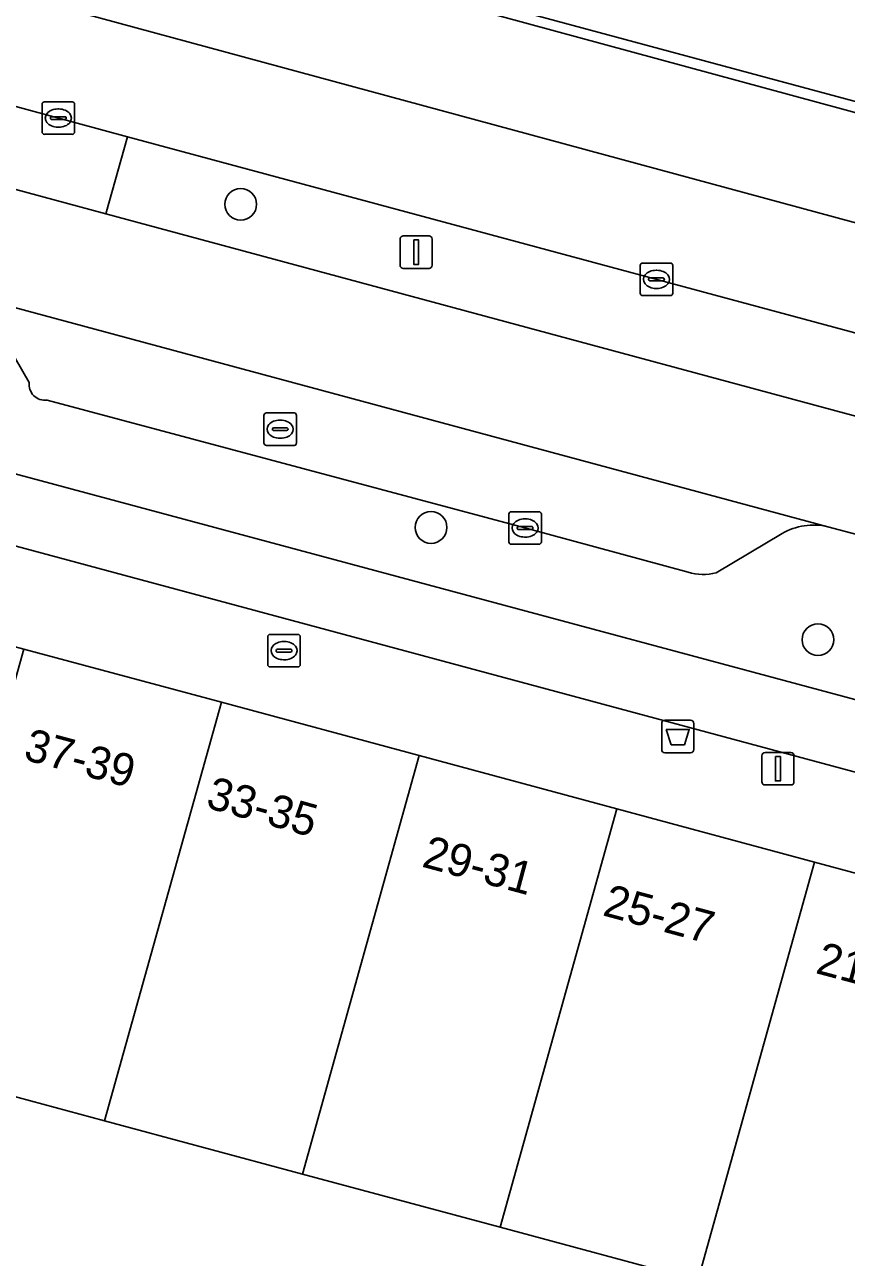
# Model space of a CAD drawing. Extents: x 160675 to 161153, y 383241 to 383714.
# Drawn here: x 160794.67 to 160819.96, y 383564.02 to 383601.94 of the extents above; entities that cross this region are included whole.
import ezdxf

# ---------------------------------------------------------------- set-up
doc = ezdxf.new("R2010")
doc.units = 0
for name, color, linetype in [('IMGEO_Afvalbak', 7, 'Continuous'), ('IMGEO_Berm_groen', 7, 'Continuous'), ('IMGEO_Berm_open', 7, 'Continuous'), ('IMGEO_Boom', 7, 'Continuous'), ('IMGEO_Brandkraan', 7, 'Continuous'), ('IMGEO_Erf', 7, 'Continuous'), ('IMGEO_Fietspad_gesloten', 7, 'Continuous'), ('IMGEO_Kolk', 7, 'Continuous'), ('IMGEO_Lichtmast', 7, 'Continuous'), ('IMGEO_OVBaan_gesloten', 7, 'Continuous'), ('IMGEO_Pand', 7, 'Continuous'), ('IMGEO_Pand_nummerreeks', 7, 'Continuous'), ('IMGEO_Parkeervlak_open', 7, 'Continuous'), ('IMGEO_Rijbaan_lokaal_gesloten', 7, 'Continuous'), ('IMGEO_Rioolput', 7, 'Continuous'), ('IMGEO_Voetpad_open', 7, 'Continuous')]:
    doc.layers.add(name, color=color, linetype=linetype)

msp = doc.modelspace()

# ---------------------------------------------------------------- linework, layer by layer
at = {"layer": 'IMGEO_Afvalbak'}
for p, q in [((160814.275, 383579.646), (160814.275, 383580.446)), ((160814.275, 383580.446), (160814.275, 383579.646)), ((160814.375, 383580.546), (160815.165, 383580.546)), ((160815.165, 383580.546), (160814.375, 383580.546)), ((160815.265, 383580.446), (160815.265, 383579.646)), ((160815.265, 383579.646), (160815.265, 383580.446)), ((160815.165, 383579.546), (160814.375, 383579.546)), ((160814.375, 383579.546), (160815.165, 383579.546))]:
    msp.add_line(p, q, dxfattribs=at)
msp.add_lwpolyline([(160814.418, 383580.26), (160815.122, 383580.26), (160814.973, 383579.79), (160814.567, 383579.79), (160814.418, 383580.26)], dxfattribs=at)
for centre, start, end in [((160814.375, 383580.446), 90, 180), ((160814.375, 383580.446), 90, 180), ((160815.165, 383580.446), 0, 90), ((160815.165, 383580.446), 360, 90), ((160814.375, 383579.646), 180, 270), ((160814.375, 383579.646), 180, 270), ((160815.165, 383579.646), 270, 0), ((160815.165, 383579.646), 270, 0)]:
    msp.add_arc(centre, 0.1, start, end, dxfattribs=at)
at = {"layer": 'IMGEO_Berm_groen'}
msp.add_lwpolyline([(160870.684, 383578.867), (160797.835, 383598.49), (160797.171, 383596.125), (160869.874, 383576.512), (160913.282, 383564.496)], dxfattribs=at)
at = {"layer": 'IMGEO_Berm_open'}
for points in [[(160771.691, 383612.444), (160783.094, 383609.33), (160861.613, 383588.006), (160861.742, 383588.359), (160845.226, 383592.848), (160809.68, 383602.419), (160784.127, 383609.308)], [(160753.356, 383599.164), (160754.374, 383598.874), (160872.54, 383567.128), (160873.601, 383566.834), (160874.194, 383569.11), (160871.092, 383569.968), (160860.355, 383572.895)], [(160794.817, 383590.934), (160793.746, 383592.772)], [(160815.088, 383585.095), (160810.069, 383586.459), (160795.367, 383590.393)], [(160826.28, 383584.667), (160819.386, 383586.497)], [(160817.978, 383586.286), (160815.949, 383585.082)]]:
    msp.add_lwpolyline(points, dxfattribs=at)
for centre, radius, start, end in [((160795.295, 383590.87), 0.482, 172.3842, 278.5611), ((160818.946, 383584.63), 1.918, 76.7407, 120.3049), ((160815.542, 383586.616), 1.587, 253.3984, 284.8716)]:
    msp.add_arc(centre, radius, start, end, dxfattribs=at)
at = {"layer": 'IMGEO_Boom'}
for centre in [(160801.324, 383596.414), (160807.18, 383586.475), (160819.082, 383583.023)]:
    msp.add_circle(centre, 0.489, dxfattribs=at)
at = {"layer": 'IMGEO_Brandkraan'}
for p, q in [((160802.155, 383582.259), (160802.155, 383583.111)), ((160802.23, 383583.185), (160803.082, 383583.185)), ((160802.643, 383582.965), (160802.668, 383582.965)), ((160803.156, 383583.111), (160803.156, 383582.259)), ((160802.414, 383582.679), (160802.414, 383582.691)), ((160802.852, 383582.642), (160802.454, 383582.642)), ((160802.457, 383582.728), (160802.855, 383582.728)), ((160802.898, 383582.691), (160802.898, 383582.679)), ((160803.082, 383582.185), (160802.23, 383582.185)), ((160802.666, 383582.405), (160802.641, 383582.405))]:
    msp.add_line(p, q, dxfattribs=at)
for points in [[(160802.155, 383582.259), (160802.155, 383583.111)], [(160802.23, 383583.185), (160803.082, 383583.185)], [(160803.156, 383583.111), (160803.156, 383582.259)], [(160803.082, 383582.185), (160802.23, 383582.185)]]:
    msp.add_lwpolyline(points, dxfattribs=at)
for centre, radius, start, end in [((160802.232, 383583.109), 0.0765, 91.552, 178.448), ((160802.232, 383583.109), 0.0765, 91.552, 178.448), ((160803.08, 383583.109), 0.0765, 1.552, 88.448), ((160803.08, 383583.109), 0.0765, 1.552, 88.448), ((160802.454, 383582.688), 0.0403, 85.8775, 175.7526), ((160802.451, 383582.678), 0.0366, 178.938, 274.7102), ((160802.855, 383582.685), 0.043, 264.8664, 352.4533), ((160802.859, 383582.69), 0.0386, 1.7309, 96.639), ((160802.232, 383582.261), 0.0765, 181.552, 268.448), ((160802.232, 383582.261), 0.0765, 181.552, 268.448), ((160803.08, 383582.261), 0.0765, 271.552, 358.448), ((160803.08, 383582.261), 0.0765, 271.552, 358.448)]:
    msp.add_arc(centre, radius, start, end, dxfattribs=at)
for centre, major_axis, ratio, start_param, end_param in [((160802.642, 383582.685), (-0.387, 0.002), 0.722429, 4.712389, 7.853982), ((160802.667, 383582.685), (-0.39, 0.002), 0.717154, 1.570796, 4.712389)]:
    msp.add_ellipse(centre, major_axis=major_axis, ratio=ratio, start_param=start_param, end_param=end_param, dxfattribs=at)
at = {"layer": 'IMGEO_Erf'}
msp.add_lwpolyline([(160815.386, 383563.308), (160809.303, 383564.947), (160803.219, 383566.585), (160797.136, 383568.224), (160791.052, 383569.862), (160784.969, 383571.501), (160778.885, 383573.14), (160772.802, 383574.778), (160766.719, 383576.417)], dxfattribs=at)
at = {"layer": 'IMGEO_Fietspad_gesloten'}
for points in [[(160741.54, 383600.127), (160851.652, 383570.489), (160869.912, 383565.633), (160904.417, 383556.04)], [(160904.814, 383558.169), (160877.012, 383565.887), (160875.567, 383566.288), (160873.601, 383566.834), (160872.54, 383567.128), (160754.374, 383598.874)]]:
    msp.add_lwpolyline(points, dxfattribs=at)
at = {"layer": 'IMGEO_Kolk'}
for p, q in [((160795.211, 383598.641), (160795.211, 383599.493)), ((160795.286, 383599.567), (160796.138, 383599.567)), ((160795.699, 383599.347), (160795.724, 383599.347)), ((160796.212, 383599.493), (160796.212, 383598.641)), ((160795.47, 383599.061), (160795.47, 383599.073)), ((160795.908, 383599.024), (160795.51, 383599.024)), ((160795.513, 383599.11), (160795.911, 383599.11)), ((160795.954, 383599.073), (160795.954, 383599.061)), ((160796.138, 383598.567), (160795.286, 383598.567)), ((160795.722, 383598.787), (160795.697, 383598.787)), ((160813.614, 383593.679), (160813.614, 383594.531)), ((160813.689, 383594.605), (160814.541, 383594.605)), ((160814.102, 383594.385), (160814.127, 383594.385)), ((160814.615, 383594.531), (160814.615, 383593.679)), ((160813.873, 383594.099), (160813.873, 383594.111)), ((160814.311, 383594.062), (160813.913, 383594.062)), ((160813.916, 383594.148), (160814.314, 383594.148)), ((160814.357, 383594.111), (160814.357, 383594.099)), ((160814.541, 383593.605), (160813.689, 383593.605)), ((160814.125, 383593.825), (160814.1, 383593.825)), ((160809.572, 383586.032), (160809.572, 383586.884)), ((160809.647, 383586.958), (160810.499, 383586.958)), ((160810.06, 383586.738), (160810.085, 383586.738)), ((160810.573, 383586.884), (160810.573, 383586.032)), ((160809.831, 383586.452), (160809.831, 383586.464)), ((160810.269, 383586.415), (160809.871, 383586.415)), ((160809.874, 383586.501), (160810.272, 383586.501)), ((160810.315, 383586.464), (160810.315, 383586.452)), ((160810.499, 383585.958), (160809.647, 383585.958)), ((160810.083, 383586.178), (160810.058, 383586.178))]:
    msp.add_line(p, q, dxfattribs=at)
for points in [[(160795.211, 383598.641), (160795.211, 383599.493)], [(160795.286, 383599.567), (160796.138, 383599.567)], [(160796.212, 383599.493), (160796.212, 383598.641)], [(160796.138, 383598.567), (160795.286, 383598.567)], [(160813.614, 383593.679), (160813.614, 383594.531)], [(160813.689, 383594.605), (160814.541, 383594.605)], [(160814.615, 383594.531), (160814.615, 383593.679)], [(160814.541, 383593.605), (160813.689, 383593.605)], [(160809.572, 383586.032), (160809.572, 383586.884)], [(160809.647, 383586.958), (160810.499, 383586.958)], [(160810.573, 383586.884), (160810.573, 383586.032)], [(160810.499, 383585.958), (160809.647, 383585.958)]]:
    msp.add_lwpolyline(points, dxfattribs=at)
for centre, radius, start, end in [((160795.288, 383599.491), 0.0765, 91.552, 178.448), ((160795.288, 383599.491), 0.0765, 91.552, 178.448), ((160796.136, 383599.491), 0.0765, 1.552, 88.448), ((160796.136, 383599.491), 0.0765, 1.552, 88.448), ((160795.51, 383599.07), 0.0403, 85.8775, 175.7526), ((160795.507, 383599.06), 0.0366, 178.938, 274.7102), ((160795.911, 383599.067), 0.043, 264.8664, 352.4533), ((160795.915, 383599.072), 0.0386, 1.7309, 96.639), ((160795.288, 383598.643), 0.0765, 181.552, 268.448), ((160795.288, 383598.643), 0.0765, 181.552, 268.448), ((160796.136, 383598.643), 0.0765, 271.552, 358.448), ((160796.136, 383598.643), 0.0765, 271.552, 358.448), ((160813.691, 383594.529), 0.0765, 91.552, 178.448), ((160813.691, 383594.529), 0.0765, 91.552, 178.448), ((160814.539, 383594.529), 0.0765, 1.552, 88.448), ((160814.539, 383594.529), 0.0765, 1.552, 88.448), ((160813.913, 383594.108), 0.0403, 85.8775, 175.7526), ((160813.91, 383594.098), 0.0366, 178.938, 274.7102), ((160814.314, 383594.105), 0.043, 264.8664, 352.4533), ((160814.318, 383594.11), 0.0386, 1.7309, 96.639), ((160813.691, 383593.681), 0.0765, 181.552, 268.448), ((160813.691, 383593.681), 0.0765, 181.552, 268.448), ((160814.539, 383593.681), 0.0765, 271.552, 358.448), ((160814.539, 383593.681), 0.0765, 271.552, 358.448), ((160809.649, 383586.882), 0.0765, 91.552, 178.448), ((160809.649, 383586.882), 0.0765, 91.552, 178.448), ((160810.497, 383586.882), 0.0765, 1.552, 88.448), ((160810.497, 383586.882), 0.0765, 1.552, 88.448), ((160809.871, 383586.461), 0.0403, 85.8775, 175.7526), ((160809.868, 383586.451), 0.0366, 178.938, 274.7102), ((160810.272, 383586.458), 0.043, 264.8664, 352.4533), ((160810.276, 383586.463), 0.0386, 1.7309, 96.639), ((160809.649, 383586.034), 0.0765, 181.552, 268.448), ((160809.649, 383586.034), 0.0765, 181.552, 268.448), ((160810.497, 383586.034), 0.0765, 271.552, 358.448), ((160810.497, 383586.034), 0.0765, 271.552, 358.448)]:
    msp.add_arc(centre, radius, start, end, dxfattribs=at)
for centre, major_axis, ratio, start_param, end_param in [((160795.698, 383599.067), (-0.387, 0.002), 0.722429, 4.712389, 7.853982), ((160795.723, 383599.067), (-0.39, 0.002), 0.717154, 1.570796, 4.712389), ((160814.101, 383594.105), (-0.387, 0.002), 0.722429, 4.712389, 7.853982), ((160814.126, 383594.105), (-0.39, 0.002), 0.717154, 1.570796, 4.712389), ((160810.059, 383586.458), (-0.387, 0.002), 0.722429, 4.712389, 7.853982), ((160810.084, 383586.458), (-0.39, 0.002), 0.717154, 1.570796, 4.712389)]:
    msp.add_ellipse(centre, major_axis=major_axis, ratio=ratio, start_param=start_param, end_param=end_param, dxfattribs=at)
at = {"layer": 'IMGEO_Lichtmast'}
for p, q in [((160806.326, 383595.443), (160807.116, 383595.443)), ((160807.116, 383595.443), (160806.326, 383595.443)), ((160806.226, 383594.543), (160806.226, 383595.343)), ((160806.226, 383595.343), (160806.226, 383594.543)), ((160807.216, 383595.343), (160807.216, 383594.543)), ((160807.216, 383594.543), (160807.216, 383595.343)), ((160807.116, 383594.443), (160806.326, 383594.443)), ((160806.326, 383594.443), (160807.116, 383594.443)), ((160817.456, 383579.554), (160818.246, 383579.554)), ((160818.246, 383579.554), (160817.456, 383579.554)), ((160817.356, 383578.654), (160817.356, 383579.454)), ((160817.356, 383579.454), (160817.356, 383578.654)), ((160818.346, 383579.454), (160818.346, 383578.654)), ((160818.346, 383578.654), (160818.346, 383579.454)), ((160818.246, 383578.554), (160817.456, 383578.554)), ((160817.456, 383578.554), (160818.246, 383578.554))]:
    msp.add_line(p, q, dxfattribs=at)
for points in [[(160806.646, 383595.318), (160806.796, 383595.318), (160806.796, 383594.568), (160806.646, 383594.568), (160806.646, 383595.318)], [(160817.776, 383579.429), (160817.926, 383579.429), (160817.926, 383578.679), (160817.776, 383578.679), (160817.776, 383579.429)]]:
    msp.add_lwpolyline(points, dxfattribs=at)
for centre, start, end in [((160806.326, 383595.343), 90, 180), ((160806.326, 383595.343), 90, 180), ((160807.116, 383595.343), 0, 90), ((160807.116, 383595.343), 360, 90), ((160806.326, 383594.543), 180, 270), ((160806.326, 383594.543), 180, 270), ((160807.116, 383594.543), 270, 0), ((160807.116, 383594.543), 270, 0), ((160817.456, 383579.454), 90, 180), ((160817.456, 383579.454), 90, 180), ((160818.246, 383579.454), 0, 90), ((160818.246, 383579.454), 360, 90), ((160817.456, 383578.654), 180, 270), ((160817.456, 383578.654), 180, 270), ((160818.246, 383578.654), 270, 0), ((160818.246, 383578.654), 270, 0)]:
    msp.add_arc(centre, 0.1, start, end, dxfattribs=at)
at = {"layer": 'IMGEO_OVBaan_gesloten'}
for points in [[(160760.567, 383616.024), (160759.368, 383616.453), (160756.884, 383613.99), (160761.763, 383612.059), (160766.781, 383610.37), (160770.415, 383609.332), (160774.938, 383608.123), (160890.249, 383576.873), (160942.076, 383562.592), (160950.815, 383560.255), (160956.785, 383559.216), (160962.841, 383558.697), (160968.725, 383558.524), (160975.387, 383558.61), (160977.148, 383558.794), (160977.505, 383562.304), (160973.835, 383561.901)], [(160973.434, 383555.262), (160976.812, 383555.49), (160977.148, 383558.794), (160975.387, 383558.61), (160968.725, 383558.524), (160962.841, 383558.697), (160956.785, 383559.216), (160950.815, 383560.255), (160942.076, 383562.592), (160890.249, 383576.873), (160774.938, 383608.123), (160770.415, 383609.332), (160766.781, 383610.37), (160761.763, 383612.059), (160756.884, 383613.99)], [(160949.177, 383564.05), (160942.127, 383565.955), (160880.388, 383583.018), (160880.346, 383582.924), (160861.613, 383588.006), (160783.094, 383609.33)], [(160765.95, 383607.15), (160797.835, 383598.49), (160870.684, 383578.867), (160946.568, 383557.927)]]:
    msp.add_lwpolyline(points, dxfattribs=at)
at = {"layer": 'IMGEO_Pand'}
for points in [[(160800.731, 383581.097), (160794.648, 383582.735), (160791.052, 383569.862), (160797.136, 383568.224)], [(160800.731, 383581.097), (160797.136, 383568.224), (160803.219, 383566.585), (160806.815, 383579.458)], [(160803.219, 383566.585), (160809.303, 383564.947), (160812.898, 383577.819), (160806.815, 383579.458)], [(160815.386, 383563.308), (160818.982, 383576.181), (160812.898, 383577.819), (160809.303, 383564.947)], [(160819.477, 383562.206), (160821.47, 383561.669), (160825.065, 383574.542), (160818.982, 383576.181), (160815.386, 383563.308)]]:
    msp.add_lwpolyline(points, close=True, dxfattribs=at)
at = {"layer": 'IMGEO_Parkeervlak_open'}
for points in [[(160819.386, 383586.497), (160792.524, 383593.731)], [(160793.746, 383592.772), (160794.817, 383590.934)], [(160795.367, 383590.393), (160810.069, 383586.459), (160815.088, 383585.095)], [(160815.949, 383585.082), (160817.978, 383586.286)]]:
    msp.add_lwpolyline(points, dxfattribs=at)
for centre, radius, start, end in [((160795.295, 383590.87), 0.482, 172.3842, 278.5611), ((160818.946, 383584.63), 1.918, 76.7407, 120.3049), ((160815.542, 383586.616), 1.587, 253.3984, 284.8716)]:
    msp.add_arc(centre, radius, start, end, dxfattribs=at)
at = {"layer": 'IMGEO_Rijbaan_lokaal_gesloten'}
for points in [[(160784.127, 383609.308), (160809.68, 383602.419), (160845.226, 383592.848), (160861.742, 383588.359), (160861.613, 383588.006), (160880.346, 383582.924), (160880.388, 383583.018), (160880.432, 383583.23), (160883.368, 383582.463), (160942.181, 383566.161)], [(160748.774, 383605.431), (160752.694, 383604.486), (160754.68, 383603.938), (160760.442, 383602.399), (160762.407, 383601.874), (160786.733, 383595.326), (160792.524, 383593.731), (160819.386, 383586.497), (160826.28, 383584.667), (160844.949, 383579.673), (160848.337, 383578.365), (160853.656, 383575.522)], [(160869.874, 383576.512), (160797.171, 383596.125), (160768.531, 383603.87)]]:
    msp.add_lwpolyline(points, dxfattribs=at)
at = {"layer": 'IMGEO_Rioolput'}
for p, q in [((160802.038, 383589.071), (160802.038, 383589.923)), ((160802.113, 383589.997), (160802.965, 383589.997)), ((160802.526, 383589.777), (160802.551, 383589.777)), ((160803.039, 383589.923), (160803.039, 383589.071)), ((160802.297, 383589.491), (160802.297, 383589.503)), ((160802.735, 383589.454), (160802.337, 383589.454)), ((160802.34, 383589.54), (160802.738, 383589.54)), ((160802.781, 383589.503), (160802.781, 383589.491)), ((160802.965, 383588.997), (160802.113, 383588.997)), ((160802.549, 383589.217), (160802.524, 383589.217))]:
    msp.add_line(p, q, dxfattribs=at)
for points in [[(160802.038, 383589.071), (160802.038, 383589.923)], [(160802.113, 383589.997), (160802.965, 383589.997)], [(160803.039, 383589.923), (160803.039, 383589.071)], [(160802.965, 383588.997), (160802.113, 383588.997)]]:
    msp.add_lwpolyline(points, dxfattribs=at)
for centre, radius, start, end in [((160802.115, 383589.921), 0.0765, 91.552, 178.448), ((160802.115, 383589.921), 0.0765, 91.552, 178.448), ((160802.963, 383589.921), 0.0765, 1.552, 88.448), ((160802.963, 383589.921), 0.0765, 1.552, 88.448), ((160802.337, 383589.5), 0.0403, 85.8775, 175.7526), ((160802.334, 383589.49), 0.0366, 178.938, 274.7102), ((160802.738, 383589.497), 0.043, 264.8664, 352.4533), ((160802.742, 383589.502), 0.0386, 1.7309, 96.639), ((160802.115, 383589.073), 0.0765, 181.552, 268.448), ((160802.115, 383589.073), 0.0765, 181.552, 268.448), ((160802.963, 383589.073), 0.0765, 271.552, 358.448), ((160802.963, 383589.073), 0.0765, 271.552, 358.448)]:
    msp.add_arc(centre, radius, start, end, dxfattribs=at)
for centre, major_axis, ratio, start_param, end_param in [((160802.525, 383589.497), (-0.387, 0.002), 0.722429, 4.712389, 7.853982), ((160802.55, 383589.497), (-0.39, 0.002), 0.717154, 1.570796, 4.712389)]:
    msp.add_ellipse(centre, major_axis=major_axis, ratio=ratio, start_param=start_param, end_param=end_param, dxfattribs=at)
at = {"layer": 'IMGEO_Voetpad_open'}
for points in [[(160768.531, 383603.87), (160797.171, 383596.125), (160797.835, 383598.49), (160765.95, 383607.15)], [(160740.618, 383600.266), (160739.966, 383597.73), (160740.363, 383597.607), (160740.309, 383597.372), (160745.98, 383595.844), (160752.064, 383594.206), (160758.147, 383592.567), (160764.231, 383590.928), (160770.314, 383589.29), (160776.398, 383587.651), (160782.481, 383586.013), (160788.565, 383584.374), (160794.648, 383582.735), (160800.731, 383581.097), (160806.815, 383579.458), (160812.898, 383577.819), (160818.982, 383576.181), (160825.065, 383574.542)], [(160851.652, 383570.489), (160741.54, 383600.127)]]:
    msp.add_lwpolyline(points, dxfattribs=at)

# ---------------------------------------------------------------- texts
at = {"layer": 'IMGEO_Pand_nummerreeks'}
for s, rotation, p in [('37-39', 344.9787, (160794.605, 383579.345)), ('33-35', 344.3072, (160800.215, 383577.868)), ('29-31', 344.9431, (160806.862, 383576.048)), ('25-27', 344.8828, (160812.424, 383574.551)), ('21-23', 345.1206, (160818.977, 383572.774))]:
    msp.add_text(s, height=1, rotation=rotation, dxfattribs=at).set_placement(p)

doc.saveas('drawing.dxf')
